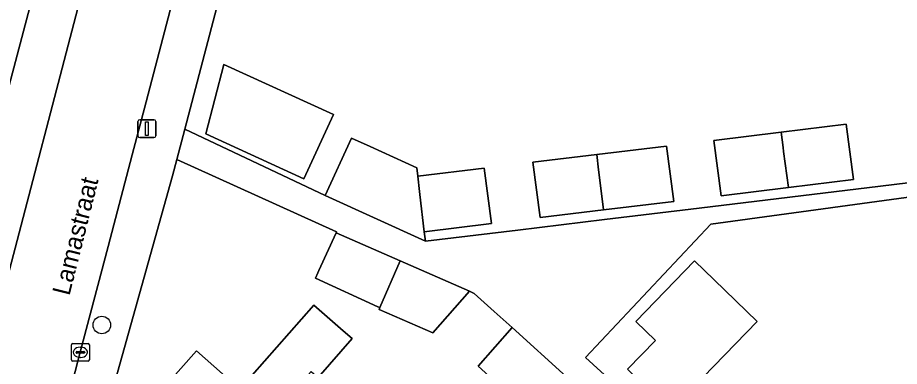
# Model space of a CAD drawing. Extents: x 163147 to 163550, y 380933 to 381639.
# Drawn here: x 163344.59 to 163393.71, y 381127.22 to 381146.66 of the extents above; entities that cross this region are included whole.
import ezdxf

# ---------------------------------------------------------------- set-up
doc = ezdxf.new("R2010")
doc.units = 0
for name, color, linetype in [('IMGEO_Boom', 7, 'Continuous'), ('IMGEO_Erf', 7, 'Continuous'), ('IMGEO_Kolk', 7, 'Continuous'), ('IMGEO_Lichtmast', 7, 'Continuous'), ('IMGEO_Openbare_ruimte_label', 7, 'Continuous'), ('IMGEO_Pand', 7, 'Continuous'), ('IMGEO_Rijbaan_lokaal_open', 7, 'Continuous'), ('IMGEO_Voetpad_open', 7, 'Continuous')]:
    doc.layers.add(name, color=color, linetype=linetype)

msp = doc.modelspace()

# ---------------------------------------------------------------- linework, layer by layer
at = {"layer": 'IMGEO_Boom'}
msp.add_circle((163349.284, 381129.527), 0.489, dxfattribs=at)
at = {"layer": 'IMGEO_Erf'}
for points in [[(163334.439, 381106.274), (163349.385, 381162.891)], [(163359.144, 381160.427), (163353.901, 381140.434), (163361.726, 381136.744), (163363.192, 381139.945), (163364.229, 381139.47), (163366.829, 381138.28), (163366.88, 381137.821), (163370.574, 381138.268), (163370.985, 381135.182), (163367.244, 381134.728), (163367.309, 381134.19), (163372.457, 381134.814), (163377.292, 381135.399), (163382.554, 381136.037), (163387.603, 381136.648), (163392.653, 381137.26), (163397.699, 381137.871)], [(163373.266, 381124.483), (163370.238, 381127.231), (163372.142, 381129.385), (163371.145, 381130.285), (163370.032, 381131.29), (163369.771, 381131.404), (163367.72, 381129.084), (163364.725, 381130.398), (163364.767, 381130.493), (163364.663, 381130.54), (163361.177, 381132.131), (163361.311, 381132.426), (163361.378, 381132.572), (163362.332, 381134.664), (163362.354, 381134.712), (163353.46, 381138.753), (163353.219, 381137.835), (163348.095, 381119.502)], [(163348.873, 381121.67), (163354.549, 381128.09), (163356.961, 381125.957), (163361.089, 381130.626), (163362.727, 381129.202), (163363.22, 381128.774), (163361.33, 381126.6)]]:
    msp.add_lwpolyline(points, dxfattribs=at)
for points in [[(163362.192, 381141.257), (163360.544, 381137.68), (163355.083, 381140.179), (163356.085, 381144.052)], [(163391.161, 381137.627), (163387.531, 381137.187), (163383.781, 381136.733), (163383.37, 381139.818), (163387.119, 381140.272), (163390.749, 381140.711)], [(163376.853, 381139.028), (163380.737, 381139.499), (163381.148, 381136.414), (163377.227, 381135.938), (163373.703, 381135.511), (163373.291, 381138.597)], [(163405.112, 381138.132), (163383.208, 381135.155), (163376.227, 381127.71), (163410.346, 381096.583), (163410.46, 381096.538), (163410.598, 381096.53), (163410.637, 381096.56), (163410.688, 381096.652), (163410.727, 381096.771)], [(163380.971, 381124.745), (163378.57, 381127.072), (163380.121, 381128.672), (163379.036, 381129.725), (163382.304, 381133.096), (163383.39, 381132.043), (163385.791, 381129.715)]]:
    msp.add_lwpolyline(points, close=True, dxfattribs=at)
at = {"layer": 'IMGEO_Kolk'}
for p, q in [((163347.585, 381127.578), (163347.585, 381128.43)), ((163347.66, 381128.504), (163348.512, 381128.504)), ((163347.887, 381128.047), (163348.285, 381128.047)), ((163348.073, 381128.284), (163348.098, 381128.284)), ((163348.586, 381128.43), (163348.586, 381127.578)), ((163347.844, 381127.998), (163347.844, 381128.01)), ((163348.282, 381127.961), (163347.884, 381127.961)), ((163348.096, 381127.724), (163348.071, 381127.724)), ((163348.328, 381128.01), (163348.328, 381127.998)), ((163348.512, 381127.504), (163347.66, 381127.504))]:
    msp.add_line(p, q, dxfattribs=at)
for points in [[(163347.585, 381127.578), (163347.585, 381128.43)], [(163347.66, 381128.504), (163348.512, 381128.504)], [(163348.586, 381128.43), (163348.586, 381127.578)], [(163348.512, 381127.504), (163347.66, 381127.504)]]:
    msp.add_lwpolyline(points, dxfattribs=at)
for centre, radius, start, end in [((163347.662, 381128.428), 0.0765, 91.552, 178.448), ((163347.662, 381128.428), 0.0765, 91.552, 178.448), ((163347.884, 381128.007), 0.0403, 85.8775, 175.7526), ((163348.289, 381128.009), 0.0386, 1.7309, 96.639), ((163348.51, 381128.428), 0.0765, 1.552, 88.448), ((163348.51, 381128.428), 0.0765, 1.552, 88.448), ((163347.662, 381127.58), 0.0765, 181.552, 268.448), ((163347.662, 381127.58), 0.0765, 181.552, 268.448), ((163347.881, 381127.997), 0.0366, 178.938, 274.7102), ((163348.285, 381128.004), 0.043, 264.8664, 352.4533), ((163348.51, 381127.58), 0.0765, 271.552, 358.448), ((163348.51, 381127.58), 0.0765, 271.552, 358.448)]:
    msp.add_arc(centre, radius, start, end, dxfattribs=at)
for centre, major_axis, ratio, start_param, end_param in [((163348.072, 381128.004), (-0.387, 0.002), 0.722429, 4.712389, 7.853982), ((163348.097, 381128.004), (-0.39, 0.002), 0.717154, 1.570796, 4.712389)]:
    msp.add_ellipse(centre, major_axis=major_axis, ratio=ratio, start_param=start_param, end_param=end_param, dxfattribs=at)
at = {"layer": 'IMGEO_Lichtmast'}
for p, q in [((163351.296, 381140.07), (163351.296, 381140.87)), ((163351.296, 381140.87), (163351.296, 381140.07)), ((163351.396, 381140.97), (163352.186, 381140.97)), ((163352.186, 381140.97), (163351.396, 381140.97)), ((163352.286, 381140.87), (163352.286, 381140.07)), ((163352.286, 381140.07), (163352.286, 381140.87)), ((163352.186, 381139.97), (163351.396, 381139.97)), ((163351.396, 381139.97), (163352.186, 381139.97))]:
    msp.add_line(p, q, dxfattribs=at)
msp.add_lwpolyline([(163351.716, 381140.845), (163351.866, 381140.845), (163351.866, 381140.095), (163351.716, 381140.095), (163351.716, 381140.845)], dxfattribs=at)
for centre, start, end in [((163351.396, 381140.87), 90, 180), ((163351.396, 381140.87), 90, 180), ((163352.186, 381140.87), 0, 90), ((163352.186, 381140.87), 360, 90), ((163351.396, 381140.07), 180, 270), ((163351.396, 381140.07), 180, 270), ((163352.186, 381140.07), 270, 0), ((163352.186, 381140.07), 270, 0)]:
    msp.add_arc(centre, 0.1, start, end, dxfattribs=at)
at = {"layer": 'IMGEO_Pand'}
for points in [[(163362.192, 381141.257), (163356.085, 381144.052), (163355.083, 381140.179), (163360.544, 381137.68)], [(163387.119, 381140.272), (163387.232, 381139.424), (163387.262, 381139.196), (163387.531, 381137.187), (163391.161, 381137.627), (163390.749, 381140.711)], [(163366.88, 381137.821), (163366.829, 381138.28), (163364.229, 381139.47), (163363.192, 381139.945), (163361.726, 381136.744), (163367.309, 381134.19), (163367.244, 381134.728), (163366.993, 381136.804), (163366.975, 381136.97)], [(163387.119, 381140.272), (163383.37, 381139.818), (163383.781, 381136.733), (163387.531, 381137.187), (163387.262, 381139.196), (163387.232, 381139.424)], [(163376.853, 381139.028), (163376.956, 381138.179), (163377.008, 381137.748), (163377.227, 381135.938), (163381.148, 381136.414), (163380.737, 381139.499)], [(163376.853, 381139.028), (163373.291, 381138.597), (163373.703, 381135.511), (163377.227, 381135.938), (163377.008, 381137.748), (163376.956, 381138.179)], [(163366.88, 381137.821), (163366.975, 381136.97), (163366.993, 381136.804), (163367.244, 381134.728), (163370.985, 381135.182), (163370.574, 381138.268)], [(163362.332, 381134.664), (163361.378, 381132.572), (163361.311, 381132.426), (163361.177, 381132.131), (163364.663, 381130.54), (163364.767, 381130.493), (163365.908, 381133.097)], [(163369.771, 381131.404), (163365.908, 381133.097), (163364.767, 381130.493), (163364.725, 381130.398), (163367.72, 381129.084)], [(163385.791, 381129.715), (163383.39, 381132.043), (163382.304, 381133.096), (163379.036, 381129.725), (163380.121, 381128.672), (163378.57, 381127.072), (163380.971, 381124.745)], [(163360.94, 381126.939), (163361.33, 381126.6), (163363.22, 381128.774), (163362.727, 381129.202), (163361.089, 381130.626), (163356.961, 381125.957), (163354.549, 381128.09), (163348.873, 381121.67), (163353.033, 381117.992)], [(163372.142, 381129.385), (163370.238, 381127.231), (163373.266, 381124.483), (163375.177, 381126.646)]]:
    msp.add_lwpolyline(points, close=True, dxfattribs=at)
at = {"layer": 'IMGEO_Rijbaan_lokaal_open'}
msp.add_lwpolyline([(163354.555, 381152.632), (163349.764, 381153.947), (163348.698, 381150.118), (163343.238, 381129.253), (163342.145, 381125.04), (163346.987, 381123.777), (163348.081, 381128.004), (163349.629, 381133.907), (163350.968, 381139.012), (163351.744, 381141.971), (163353.081, 381147.071), (163353.695, 381149.411)], close=True, dxfattribs=at)
at = {"layer": 'IMGEO_Voetpad_open'}
for points in [[(163353.901, 381140.434), (163359.144, 381160.427), (163360.74, 381162.963)], [(163349.385, 381162.891), (163334.439, 381106.274), (163328.748, 381100.437), (163328.567, 381100.252), (163327.566, 381099.224), (163327.46, 381099.116), (163325.705, 381097.476), (163310.741, 381082.456), (163311.048, 381082.128), (163310.809, 381081.904), (163310.55, 381082.181), (163308.363, 381080.136), (163308.588, 381079.896), (163307.821, 381079.179), (163307.591, 381079.425), (163305.465, 381077.436), (163305.767, 381077.113), (163305.592, 381076.949), (163307.948, 381074.335), (163325.917, 381092.562), (163328.54, 381095.222), (163335.379, 381102.16)], [(163336.678, 381104.171), (163337.355, 381106.775), (163338.283, 381110.344), (163340.318, 381118.106), (163341.295, 381121.826), (163342.145, 381125.04), (163343.238, 381129.253), (163348.698, 381150.118), (163349.764, 381153.947), (163350.589, 381157.148), (163351.104, 381159.046), (163351.813, 381161.75)], [(163356.417, 381159.792), (163355.84, 381157.594), (163355.385, 381155.82), (163354.555, 381152.632), (163353.695, 381149.411), (163353.081, 381147.071), (163351.744, 381141.971), (163350.968, 381139.012), (163349.629, 381133.907), (163348.081, 381128.004), (163346.987, 381123.777), (163346.138, 381120.581), (163345.643, 381118.859)], [(163348.095, 381119.502), (163353.219, 381137.835), (163353.46, 381138.753), (163353.901, 381140.434)], [(163397.699, 381137.871), (163392.653, 381137.26), (163387.603, 381136.648), (163382.554, 381136.037), (163377.292, 381135.399), (163372.457, 381134.814), (163367.309, 381134.19), (163361.726, 381136.744), (163353.901, 381140.434), (163353.46, 381138.753), (163362.354, 381134.712), (163362.332, 381134.664), (163365.908, 381133.097), (163369.771, 381131.404), (163370.032, 381131.29), (163371.145, 381130.285), (163372.142, 381129.385), (163375.177, 381126.646)]]:
    msp.add_lwpolyline(points, dxfattribs=at)
msp.add_lwpolyline([(163410.727, 381096.771), (163410.688, 381096.652), (163410.637, 381096.56), (163410.598, 381096.53), (163410.46, 381096.538), (163410.346, 381096.583), (163376.227, 381127.71), (163383.208, 381135.155), (163405.112, 381138.132)], close=True, dxfattribs=at)

# ---------------------------------------------------------------- texts
at = {"layer": 'IMGEO_Openbare_ruimte_label'}
msp.add_text('Lamastraat', height=1, rotation=75.936, dxfattribs=at).set_placement((163347.476, 381131.12))

doc.saveas('drawing.dxf')
